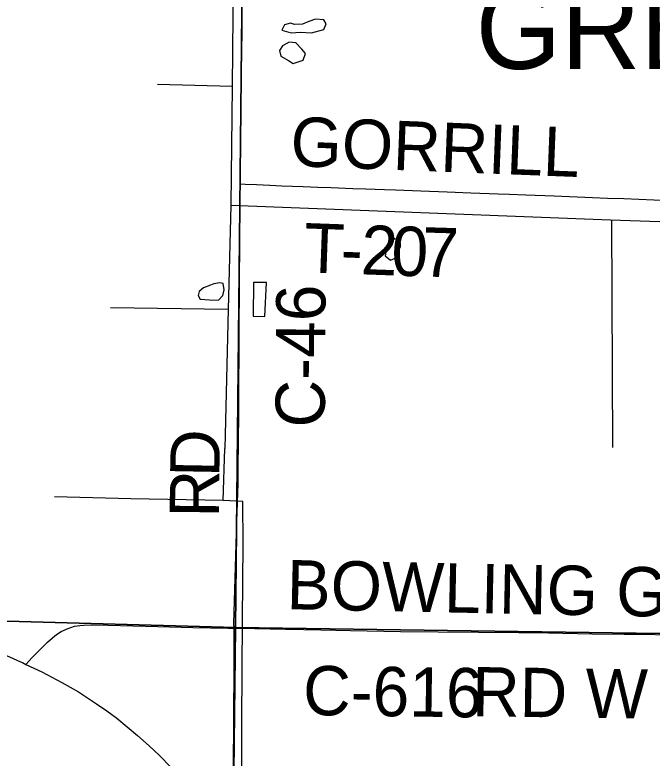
# Model space of a CAD drawing. Extents: x 1443599 to 1910620, y 1028088 to 1361369.
# Drawn here: x 1635252 to 1639132, y 1229853 to 1234375 of the extents above; entities that cross this region are included whole.
import ezdxf

# ---------------------------------------------------------------- set-up
doc = ezdxf.new("R2010")
doc.units = 0
for name, color, linetype in [('GM_X_Corporation_Text', 7, 'Continuous'), ('GM_X_County_Road', 7, 'Continuous'), ('GM_X_County_Road_Text', 7, 'Continuous'), ('GM_X_Minor_Lake', 7, 'Continuous'), ('GM_X_Minor_River', 7, 'Continuous'), ('GM_X_Section', 7, 'Continuous'), ('GM_X_Township_Road', 7, 'Continuous'), ('GM_X_Township_Road_Text', 7, 'Continuous'), ('GM_X_US_Route', 7, 'Continuous')]:
    doc.layers.add(name, color=color, linetype=linetype)

msp = doc.modelspace()

# ---------------------------------------------------------------- linework, layer by layer
at = {"layer": 'GM_X_County_Road'}
for points in [[(1636624.4, 1233346.4), (1636627.7, 1233639.1), (1636630.8, 1233901.6), (1636636.3, 1234278.9), (1636637, 1234377.4), (1636644.5, 1234787.4), (1636650.7, 1235131.8), (1636659.7, 1235574.6), (1636662.9, 1235820.7), (1636665.8, 1235951.8), (1636666.7, 1235993.1)], [(1636614.5, 1231791), (1636615.8, 1231933.1), (1636616.3, 1232146.4), (1636618.5, 1232294), (1636618.2, 1232441.7), (1636620.4, 1232737), (1636620.9, 1232835.4), (1636621.3, 1232901), (1636622.4, 1233163.4), (1636624.4, 1233346.4)], [(1636586.5, 1230643.4), (1636586.4, 1230670.4), (1636602.8, 1231293.4), (1636612.8, 1231523), (1636612.7, 1231605), (1636614.5, 1231791)], [(1635320, 1230423.5), (1635357.8, 1230465.3), (1635409.8, 1230517.8), (1635451, 1230557.7), (1635481.4, 1230584.9), (1635506.7, 1230605.1), (1635533.6, 1230623), (1635547.7, 1230630.6), (1635569.8, 1230640.6), (1635592.4, 1230648.8), (1635615.8, 1230655.2), (1635647.6, 1230660.7), (1635671.9, 1230663), (1635712.6, 1230664.4), (1635819.2, 1230662.6), (1636122.7, 1230654.1), (1636336, 1230648.8), (1636549.3, 1230644), (1636586.5, 1230643.4)], [(1636583.8, 1229392.1), (1636581.2, 1229440.2), (1636582.7, 1229522), (1636584.2, 1229817.4), (1636585.1, 1230063.5), (1636586.9, 1230440.7), (1636586.5, 1230643.4)], [(1636586.5, 1230643.4), (1636713.5, 1230641.5), (1636899.3, 1230637.9), (1637012.1, 1230635.7), (1637115.4, 1230633.7), (1637295.9, 1230629.9), (1637599.4, 1230624.4), (1637829.2, 1230622.1), (1638075.3, 1230618.9), (1638321.4, 1230617.3), (1638501.8, 1230614.7), (1638764.4, 1230609.6), (1638961.3, 1230607.3), (1639076.2, 1230607), (1639228.7, 1230604.1), (1639381.7, 1230601.2), (1639608.3, 1230594.6), (1639829.8, 1230585.9)]]:
    msp.add_lwpolyline(points, dxfattribs=at)
at = {"layer": 'GM_X_Minor_Lake'}
for p, q in [((1637041.6, 1234334.2), (1637003.2, 1234318.9)), ((1637000.3, 1234166.4), (1636963, 1234205.2)), ((1637516.3, 1232964.6), (1637511.9, 1232942.6)), ((1636464.5, 1232739.5), (1636444.3, 1232729.8)), ((1636785.1, 1232747.5), (1636705, 1232747))]:
    msp.add_line(p, q, dxfattribs=at)
for points in [[(1637003.2, 1234318.9), (1636955.1, 1234315.8), (1636931.2, 1234324.3), (1636893, 1234314.9), (1636878.3, 1234281.1), (1636934.1, 1234266), (1636992.3, 1234268.9), (1637058.3, 1234265.7), (1637132.8, 1234286.4), (1637147.5, 1234320.2), (1637133.9, 1234344.5), (1637081.9, 1234349.5), (1637041.6, 1234334.2)], [(1636963, 1234205.2), (1636923, 1234210), (1636882.5, 1234186.7), (1636864, 1234158.9), (1636871.4, 1234124.7), (1636918.9, 1234097.7), (1636946.6, 1234079.1), (1637007.1, 1234100.1), (1637021.9, 1234139.9), (1637000.3, 1234166.4)], [(1637511.9, 1232942.6), (1637507.3, 1232908.6), (1637538.8, 1232881.9), (1637567.1, 1232895.4), (1637600.5, 1232965.1), (1637597.3, 1233009.3), (1637565.3, 1233011.9), (1637532.8, 1232988.4), (1637516.3, 1232964.6)], [(1636444.3, 1232729.8), (1636399.9, 1232714.6), (1636373.4, 1232693), (1636368.9, 1232667), (1636380.5, 1232644.7), (1636436.6, 1232641.7), (1636492.6, 1232638.6), (1636519.2, 1232668.2), (1636525.9, 1232702.2), (1636520.6, 1232740.5), (1636500.6, 1232744.8), (1636464.5, 1232739.5)], [(1636705, 1232747), (1636703.1, 1232542.4), (1636775.1, 1232539), (1636785.1, 1232747.5)]]:
    msp.add_lwpolyline(points, dxfattribs=at)
at = {"layer": 'GM_X_Minor_River'}
for points in [[(1636629.9, 1239445.6), (1636611.2, 1238675.2), (1636598.8, 1237597.8), (1636591.3, 1236676.7), (1636596.3, 1235883.9), (1636595.8, 1235542.7), (1636590.2, 1234930.7), (1636579.6, 1234371), (1636575.4, 1233939.6), (1636567.7, 1233217.2), (1636551.6, 1232583.3), (1636531.5, 1231736.8)], [(1636575.4, 1233939.6), (1636120.9, 1233952.1)], [(1636567.7, 1233217.2), (1638879.5, 1233127.7), (1640679.1, 1233067.7), (1640644.8, 1232105)], [(1638885.4, 1233123.6), (1638891.3, 1231742.7)], [(1636551.6, 1232583.3), (1635834.7, 1232592.8)], [(1636520.1, 1231420.1), (1636531.5, 1231736.8)], [(1636644.4, 1223438), (1636630.9, 1223614.5), (1636613.1, 1223676.8), (1636595.2, 1223710.9), (1636575.3, 1223765.1), (1636569.6, 1223875.5), (1636570, 1225333.8), (1636614.6, 1226866.2), (1636626.5, 1228134), (1636632.4, 1229453.9), (1636634.3, 1230073.7), (1636638.2, 1230697.6), (1636641.5, 1231154.9), (1636640.3, 1231413.7), (1636520.1, 1231420.1), (1635959.2, 1231431.7), (1635494.5, 1231443.1)]]:
    msp.add_lwpolyline(points, dxfattribs=at)
at = {"layer": 'GM_X_Section'}
for points in [[(1631310.2, 1236085), (1636650.8, 1235966.8), (1636595.3, 1230648.8), (1631247.2, 1230796.7)], [(1636650.8, 1235966.8), (1642066.7, 1235791.6), (1641921.5, 1230497.2), (1640040.1, 1230599.8), (1636595.3, 1230648.8)], [(1631247.2, 1230796.7), (1636595.3, 1230648.8), (1636534.6, 1225385.5), (1631218.1, 1225507)], [(1636595.3, 1230648.8), (1640040.1, 1230599.8), (1641921.5, 1230497.2), (1641860.6, 1225227.8), (1636534.6, 1225385.5)]]:
    msp.add_lwpolyline(points, close=True, dxfattribs=at)
at = {"layer": 'GM_X_Township_Road'}
msp.add_lwpolyline([(1636624.4, 1233346.4), (1636654.2, 1233345.2), (1636723, 1233342.6), (1636804.9, 1233338.5), (1636877, 1233335.3), (1637008.3, 1233330.3), (1637096.8, 1233327.7), (1637178.8, 1233325), (1637309.9, 1233319.7), (1637388.7, 1233316.8), (1637503.4, 1233312.2), (1637569, 1233310), (1637723.1, 1233304.1), (1637883.8, 1233297.6), (1638028.1, 1233292.8), (1638195.3, 1233286.1), (1638264.2, 1233283.7), (1638362.6, 1233280.3), (1638536.4, 1233273.6), (1638769.2, 1233264), (1638861, 1233260.6), (1638959.4, 1233257.3), (1639234.8, 1233246.6)], dxfattribs=at)
at = {"layer": 'GM_X_US_Route'}
for points in [[(1633968.4, 1230701.8), (1634080.4, 1230699.3), (1634234.7, 1230693.4), (1634329.8, 1230687.7), (1634411.7, 1230679.9), (1634506.3, 1230667.9), (1634606.9, 1230651.8), (1634694.2, 1230635.8), (1634761.8, 1230621.4), (1634828.9, 1230605.1), (1634905, 1230584.1), (1634980.5, 1230560.9), (1635048.9, 1230537.2), (1635140.9, 1230501.8), (1635220, 1230469.3), (1635286.8, 1230439.6)], [(1635286.8, 1230439.6), (1635298.1, 1230434.6), (1635320, 1230423.5), (1635416, 1230377.7), (1635538.2, 1230312.6), (1635638.8, 1230255.6), (1635750, 1230184.1), (1635812, 1230140.7), (1635872.5, 1230095.4), (1635936.9, 1230044.2), (1635999.7, 1229991.2), (1636070.8, 1229927.7), (1636132.8, 1229868.8), (1636202.3, 1229798.9)]]:
    msp.add_lwpolyline(points, dxfattribs=at)

# ---------------------------------------------------------------- texts
at = {"layer": 'GM_X_Corporation_Text'}
msp.add_text('GREEN', height=500, rotation=0, dxfattribs=at).set_placement((1638057.7, 1234046.3))
at = {"layer": 'GM_X_County_Road_Text'}
for s, rotation, p in [('C-46', 89.6646, (1637138.9, 1231864)), ('D', 88.9508, (1636496.9, 1231561.2)), ('R', 89.4653, (1636494.6, 1231315.6)), ('BOWLING GREEN', 358.8439, (1636905.1, 1230759.4)), ('C-616', 359.1792, (1637005.4, 1230115.8)), ('RD W', 359.2109, (1638034.2, 1230108.1))]:
    msp.add_text(s, height=300, rotation=rotation, dxfattribs=at).set_placement(p)
at = {"layer": 'GM_X_Township_Road_Text'}
for s, rotation, p in [('GORRILL', 357.7853, (1636926.3, 1233456.4)), ('T', 357.9468, (1637008.2, 1232809.3)), ('2', 357.9614, (1637355.7, 1232796.9)), ('0', 358.0262, (1637540.7, 1232790.3)), ('7', 358.292, (1637726.9, 1232783.9)), ('-', 357.9387, (1637232.4, 1232801.3))]:
    msp.add_text(s, height=300, rotation=rotation, dxfattribs=at).set_placement(p)

doc.saveas('drawing.dxf')
